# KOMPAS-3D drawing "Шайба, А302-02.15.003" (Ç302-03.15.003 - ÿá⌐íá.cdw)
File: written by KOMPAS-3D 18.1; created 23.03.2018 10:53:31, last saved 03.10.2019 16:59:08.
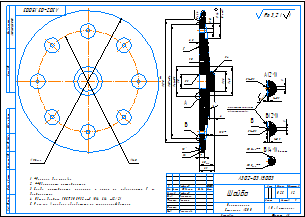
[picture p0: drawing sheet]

Sheet 1: A3, landscape

Document properties: Автор: Милов; Масса: 0.249827; Параметр неуказанной шероховатости: Ra 3,2; Полное имя файла: ..\3Д ПВХ\А302-01.15.003 - Шайба.m3d; Организация: Милов

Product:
- Part/product: Шайба  | designation А302-02.15.003
    Материал: Полипропилен  ГОСТ 26996-86 (density 900 kg/m3)
    Масса: 0.246184
    Раздел спецификации: Детали
    Форматы листов документа: A4
- Part/product: Шайба  | designation А302-01.15.003
    Масса: 0.292092
    Раздел спецификации: Детали
    Форматы листов документа: A4
- Part/product: Шайба  | designation А302-02.15.003
    Материал: Поливинилхлорид (density 1350 kg/m3)
    Масса: 0.432682
    Раздел спецификации: Детали
    Форматы листов документа: A4
- Part/product: Шайба  | designation А302-03.15.003
    Материал: Полипропилен  ГОСТ 26996-86 (density 900 kg/m3)
    Масса: 0.28231
    Раздел спецификации: Детали
    Форматы листов документа: A4
    source file: А302-03.15.003 - Шайба.cdw
- Part/product: Шайба  | designation А302-03.15.003-01
    Материал: Полипропилен  ГОСТ 26996-86 (density 900 kg/m3)
    Масса: 0.249827
    Раздел спецификации: Детали
    Форматы листов документа: A4
    source file: ..\Чертежи ПВХ\А302-02.15.003 - Шайба.cdw, А302-03.15.003 - Шайба.cdw

Title block, sheet 1: Наименование: Шайба; designation: А302-03.15.003; Материал: Полипропилен / Стержень  200; Масса: 0,25; scale: 1:2; Количество листов документа: 1; organisation: АО «Астерион»; Форматы листов документа: A3; stored path: \\192.168.87.28\Konstructor_doc\Мембранные насосы\Мембранный электропривод\А302-00.00.000 - ASTRA-302 (МЭ200)\Чертежи\А302-00.15.003 - Шайба.cdw; Разработал: Лифлянд; Проверил: Борисенко; Т. контр.: Лучихин; Утвердил: Григорьева

Views: Вид 1, Местный разрез 1, Спереди, Проекционный вид 2, Выносной элемент 3, Выносной элемент 4, Выносной элемент 5, Выносной элемент А, Выносной элемент, Выносной элемент Б, Выносной элемент В
Referenced files in D:\Мембранные насосы\Мембранный электропривод\А302-00.00.000 - ASTRA-302 (МЭ200)\3Д ПВХ\: А302-01.15.003 - Шайба.m3d
Referenced files in Z:\Мембранные насосы\Мембранный электропривод\А302-00.00.000 - ASTRA-302 (МЭ200)\3Д\: А302-00.15.003 - Шайба.m3d
Referenced files in Z:\Мембранные насосы\Мембранный электропривод\А302-00.00.000 - ASTRA-302 (МЭ200)\3Д ПВХ\: А302-01.15.003 - Шайба.m3d
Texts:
  Ra 1,6
  Зона контакта с мембраной
  поверхность глянцевая
  Ra 0,80
  Ra 3,2
  Ra 3,2 ( )
Dimensions and other numbers on the sheet: 6,5; 40; 28; 4; 6; 20; 3; 10; 13,5; 41±0,3; 157±0,4; 7; 170; 2; 5; 24; 8 отв.; 1; 21; 196; 140; 0,5; 1:2; 0,25; 03.10.2019; 01

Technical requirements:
  *Размеры для справок.
  **Обеспечить инструментом.
  Следы инструмента, царапины и риски на поверхности  Г  не
  допускаются.
  Общие допуски ГОСТ 30893.2-mK (H14, h14,  t2/2).
  Размеры в скобках обработать по сопрягаемой детали.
